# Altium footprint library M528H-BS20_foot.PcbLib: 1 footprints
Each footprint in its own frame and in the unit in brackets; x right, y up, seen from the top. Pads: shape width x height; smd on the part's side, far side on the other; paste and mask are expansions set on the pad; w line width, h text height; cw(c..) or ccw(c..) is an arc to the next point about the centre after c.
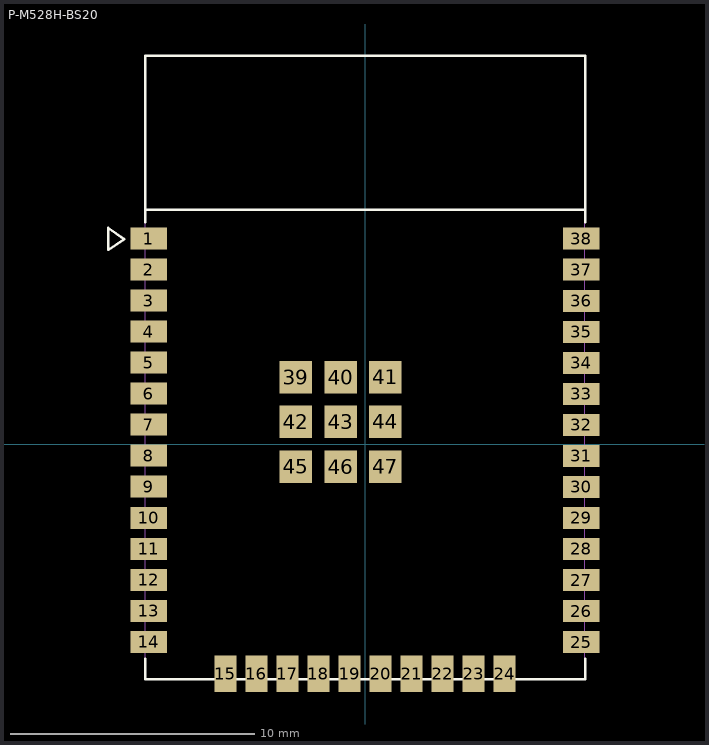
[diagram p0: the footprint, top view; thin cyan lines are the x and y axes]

## P-M528H-BS20 [mm]
pads (47):
  rect 1.5x0.9 smd: 1(-8.85,8.418) 2(-8.85,7.148) 3(-8.85,5.878) 4(-8.85,4.608) 5(-8.85,3.338) 6(-8.85,2.068) 7(-8.85,0.798) 8(-8.85,-0.472) 9(-8.85,-1.742) 10(-8.85,-3.012) 11(-8.85,-4.282) 12(-8.85,-5.552) 13(-8.85,-6.822) 14(-8.85,-8.092) 25(8.85,-8.1) 26(8.85,-6.83) 27(8.85,-5.56) 28(8.85,-4.29) 29(8.85,-3.02) 30(8.85,-1.75) 31(8.85,-0.48) 32(8.85,0.79) 33(8.85,2.06) 34(8.85,3.33) 35(8.85,4.6) 36(8.85,5.87) 37(8.85,7.14) 38(8.85,8.41)
  rect 0.9x1.5 smd: 15(-5.715,-9.4) 16(-4.445,-9.4) 17(-3.175,-9.4) 18(-1.905,-9.4) 19(-0.635,-9.4) 20(0.635,-9.4) 21(1.905,-9.4) 22(3.175,-9.4) 23(4.445,-9.4) 24(5.715,-9.4)
  rrect0% 1.33x1.33 smd: 39(-2.835,2.745) 40(-1,2.745) 41(0.835,2.745) 42(-2.835,0.911) 43(-1,0.911) 44(0.835,0.911) 45(-2.835,-0.925) 46(-1,-0.925) 47(0.835,-0.925)
Top Overlay:
  lines w0.1: -9,-8.781 -9,-9.615 6.476,-9.615 ; -9,9.092 -9,15.895 9.017,15.895 9.017,9.092 ; -8.981,9.595 9.003,9.595 ; 6.396,-9.615 9.017,-9.615 9.017,-8.781 ; -10.503,7.952 -9.862,8.389 -10.503,8.854 -10.503,7.98 -10.503,7.952
Mechanical120:
  lines w0.051: -9,-9.6 -9,9.6 9,9.6 9,-9.6 -9,-9.6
